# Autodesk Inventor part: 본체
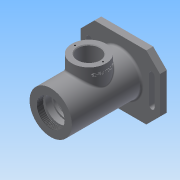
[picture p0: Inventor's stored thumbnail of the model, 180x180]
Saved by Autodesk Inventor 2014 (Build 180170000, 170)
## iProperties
Created: 2017-10
Part Number: 본체
Material: 일반
Document SubType Name: Modeling
Designer: net
Density: 1 g/cm^3
Appearance: 기본값
Mass: 273.306 g
Surface Area: 656.095 cm^2
Volume: 273.306 cm^3
Author: net
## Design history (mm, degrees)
sketch "스케치1"
  geometry: L1 (-58, 47)-(58, 47); L2 (58, 47)-(58, -47); L3 (58, -47)-(-58, -47); L4 (-58, -47)-(-58, 47); 3 further points
  constraints: 8 end point, 2 midpoint, 2 parallel, 1 horizontal, 1 horizontal alignment, 1 perpendicular, 1 vertical alignment
  dimensions: "d1" = 94 distance of L1.end L2.end; "d2" = 116 distance of L2.end L3.end
extrude "돌출1" new body sketch "스케치1" distance "d3" = 10; taper "d4" = 0 deg
sketch "스케치2"
  geometry: C1 r 35 at (0, 0); 1 further point
  constraints: 1 centre point, 1 coincident
  dimensions: "d5" = 70 diameter of C1
extrude "돌출2" join sketch "스케치2" distance "d6" = 3; taper "d7" = 0 deg
sketch "스케치3"
  geometry: C1 r 31 at (0, 0); 1 further point
  constraints: 1 centre point, 1 coincident
  dimensions: "d8" = 62 diameter of C1
extrude "돌출3" join sketch "스케치3" distance "d9" = 102; taper "d10" = 0 deg
sketch "스케치4"
  geometry: L1 (-31, -102)-(31, -102) reference; L2 (31, 0)-(-31, 0) reference; L3 (-47, 0)-(47, 0) reference; L4 (-47, 0)-(-47, 10) reference; L5 (47, 10)-(-47, 10) reference; L6 (47, 0)-(47, 10) reference; L7 (-35, 10)-(35, 10) reference; L8 (35, 13)-(-35, 13) reference; L9 (0, 13)-(0, -102); L10 (0, -93)-(-24, -93); L11 (-24, -93)-(-24, -90); L12 (-24, -90)-(-20, -90); L13 (-20, -90)-(-20, -81); L14 (-20, -81)-(-17.5, -81); L15 (-17.5, -81)-(-17.5, -77.75); L16 (-17.5, -77.75)-(-18.5, -77.75); L17 (-18.5, -77.75)-(-18.5, -76); L18 (-18.5, -76)-(-17.5, -76); L19 (-17.5, -76)-(-17.5, -65); L20 (-17.5, -65)-(-26, -65); L21 (-26, -65)-(-26, -27); L22 (-26, -27)-(-17.5, -27); L23 (-17.5, -27)-(-17.5, -16); L24 (-17.5, -16)-(-16.5, -16); L25 (-16.5, -16)-(-16.5, -11); L26 (-16.5, -11)-(-10, -11); L27 (-10, -11)-(-10, -8.3); L28 (-10, -8.3)-(-12.5, -8.3); L29 (-12.5, -8.3)-(-12.5, -1); L30 (-12.5, -1)-(-16, -1); L31 (-16, -1)-(-22, 13); 1 further point
  constraints: 46 end point, 14 parallel, 3 collinear, 2 midpoint, 2 perpendicular, 2 point on line
  dimensions: "d12" = 3 distance of L10.end L11.end; "d13" = 21 distance between parallel lines of L14 L1; "d14" = 26 distance between parallel lines of L1 L18; "d15" = 60 distance between parallel lines of L24 L18; "d16" = 38 distance of L20.end L21.end; "d18" = 14 distance between parallel lines of L30 L8; "d19" = 12 distance between parallel lines of L1 L12; "d20" = 48 diameter of L11 L9; "d21" = 40 diameter of L13 L9; "d23" = 35 diameter of L15 L9; "d24" = 11 distance of L22.end L23.end; "d25" = 35 diameter of L19 L9; "d26" = 52 diameter of L21 L9; "d27" = 37 diameter of L17 L9; "d28" = 1.75 distance of L16.end L17.end; "d30" = 5 distance of L24.end L25.end; "d31" = 2.7 distance of L26.end L27.end; "d32" = 25 diameter of L29 L9; "d33" = 20 diameter of L27 L9; "d34" = 33 diameter of L25 L9; "d35" = 32 diameter of L30.end L9; "d36" = 44 diameter of L31.end L9
revolve "회전1" sketch "스케치4" stored, may be unused: angle "d37" = 90 deg
hole "구멍1" diameter "d40" = 40.376; stored, may be unused: countersink angle "d44" = 90 deg, drill point angle "d46" = 0 deg; dims "d38" = 10, "d39" = 10, "d41" = 9, "d42" = 4, "d43" = 2, "d45" = 9
sketch "스케치5"
  geometry: L1 (0, 0)-(116, 0) reference; L2 (89, 102)-(27, 102) reference; L3 (27, 0)-(89, 0) reference; L4 (0, 0)-(116, 0) reference; L5 (0, 0)-(0, -10) reference; L6 (116, -10)-(0, -10) reference; L7 (116, 0)-(116, -10) reference; C1 r 25 at (58, 46); 2 further points
  constraints: 1 centre point, 1 midpoint, 1 vertical alignment
  dimensions: "d47" = 50 diameter of C1; "d48" = 56 distance from line of C1.centre L2
extrude "돌출4" join sketch "스케치5" stored distance "d49" = 102; taper "d50" = 0 deg
hole "구멍2" diameter "d53" = 32; stored, may be unused: countersink angle "d57" = 90 deg, drill point angle "d59" = 0 deg; dims "d51" = 10, "d52" = 10, "d54" = 9, "d55" = 4, "d56" = 2, "d58" = 47
sketch "스케치6"
  geometry: L1 (-58, 47)-(-58, -47) reference; L2 (-46, 20)-(-46, -20); L3 (-50, 20)-(-50, -20); L4 (-42, -20)-(-42, 20); L5 (46, 20)-(46, -20); L6 (42, 20)-(42, -20); L7 (50, -20)-(50, 20); C1 r 35 at (0, 0) reference; A1 r 4 centre (-46, 20) between (-42, 20) and (-50, 20); A2 r 4 centre (-46, -20) between (-50, -20) and (-42, -20); A3 r 4 centre (46, 20) between (50, 20) and (42, 20); A4 r 4 centre (46, -20) between (42, -20) and (50, -20); 2 further points
  constraints: 16 end point, 8 point on circle, 8 tangent, 5 parallel, 4 centre point, 3 horizontal alignment, 2 midpoint, 1 equal radius
  dimensions: "d60" = 40 distance of L2.start L2.end; "d61" = 4 radius of A1; "d62" = 46 distance from line of L2 C1.centre; "d63" = 46 distance from line of L5 C1.centre
extrude "돌출5" cut sketch "스케치6" stored distance "d64" = 102; taper "d65" = 0 deg
chamfer "모따기1" distance "d66" = 20; stored, may be unused: second distance "d67" = 2, angle "d68" = 45 deg
node "작업 평면1"
sketch "스케치7"
  geometry: L1 (0, -25)-(0, 25) reference; L2 (16, -56)-(78, -56) reference; 2 further points
  constraints: 1 other
  dimensions: "d69" = 10 distance from line of point (10, 0) L1; "d70" = 56 distance from line of L2 point (10, 0)
feature "엠보싱1" sketch "스케치7" dims "d1" = 94, "d2" = 116, "d71" = 0.5, "d72" = 0
sketch "스케치8"
  geometry: C1 r 16 at (0, 0) reference; 2 further points
  constraints: 1 horizontal alignment
  dimensions: "d73" = 20.5 distance of C1.centre point (20.5, 0)
hole "구멍3" sketch "스케치8" at (20.5, 0) diameter "d74" = 2.459; stored, may be unused: countersink angle "d78" = 90 deg, drill point angle "d80" = 118 deg; dims "d75" = 6, "d76" = 4, "d77" = 2, "d79" = 8
chamfer "모따기2" distance "d84" = 0.7; stored, may be unused: second distance "d85" = 2, angle "d86" = 30 deg
chamfer "모따기3" distance "d87" = 1; stored, may be unused: second distance "d88" = 2, angle "d89" = 30 deg
fillet "모깎기1" dims "d90" = 0.3
fillet "모깎기2" dims "d91" = 0.3
fillet "모깎기3" dims "d92" = 3
fillet "모깎기4" dims "d93" = 3
node "솔리드1"
pattern_circular "원형 패턴1" dims angle "d82" = 360 deg
node "투영된 루프1"
node "투영된 루프2"
node "투영된 루프3"
node "투영된 루프4"
